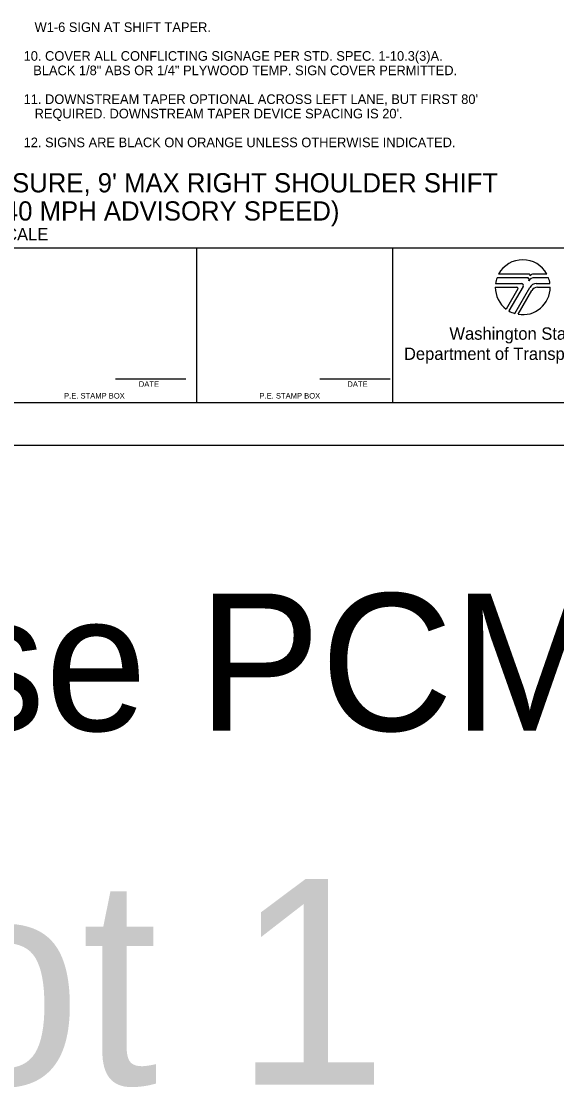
# Model space of a CAD drawing. Extents: x 99999 to 100116, y 99995 to 100013.
# Drawn here: x 100007.6 to 100011.5, y 99995.01 to 100002.78 of the extents above; entities that cross this region are included whole.
import ezdxf

# ---------------------------------------------------------------- set-up
doc = ezdxf.new("R2010")
doc.units = 0
for name, color, linetype in [('SH_DE_DetailHeading1Text', 7, 'Continuous'), ('SH_GI_GeneralNotesBodyText', 7, 'Continuous'), ('SH_GI_PlotLimits', 7, 'Continuous'), ('SH_GI_SheetBorder', 7, 'Continuous'), ('SH_GI_SheetLocationText', 7, 'Continuous'), ('SH_GI_SheetTextInCells', 7, 'Continuous'), ('SH_GI_WSDOTLogo', 7, 'Continuous')]:
    doc.layers.add(name, color=color, linetype=linetype)

msp = doc.modelspace()

# ---------------------------------------------------------------- linework, layer by layer
at = {"layer": 'SH_GI_PlotLimits'}
msp.add_lwpolyline([(99999.0625, 99999.6875), (100016.0625, 99999.6875), (100016.0625, 100010.6875), (99999.0625, 100010.6875)], close=True, dxfattribs=at)
at = {"layer": 'SH_GI_SheetBorder'}
for p, q in [((100000, 100001.1259), (100015.75, 100001.1259)), ((100008.8828, 100000), (100008.8828, 100001.1259)), ((100010.3089, 100001.1259), (100010.3089, 100000)), ((100008.2903, 100000.1733), (100008.802, 100000.1733)), ((100009.7797, 100000.1733), (100010.2914, 100000.1733)), ((100000, 100000), (100015.75, 100000))]:
    msp.add_line(p, q, dxfattribs=at)
at = {"layer": 'SH_GI_WSDOTLogo'}
for p, q in [((100011.059, 100000.8661), (100011.2496, 100000.8661)), ((100011.2894, 100000.9094), (100011.0697, 100000.9094)), ((100011.303, 100000.9354), (100011.0815, 100000.9354)), ((100011.433, 100000.9354), (100011.3351, 100000.9354)), ((100011.343, 100000.9094), (100011.3429, 100000.9094)), ((100011.4448, 100000.9094), (100011.343, 100000.9094)), ((100011.3558, 100000.8661), (100011.4555, 100000.8661)), ((100011.0572, 100000.84), (100011.2148, 100000.84)), ((100011.222, 100000.8277), (100011.1364, 100000.6807)), ((100011.261, 100000.8464), (100011.1567, 100000.6672)), ((100011.1989, 100000.6487), (100011.3089, 100000.839)), ((100011.2244, 100000.6428), (100011.3242, 100000.8156)), ((100011.3655, 100000.8394), (100011.4572, 100000.8394))]:
    msp.add_line(p, q, dxfattribs=at)
for centre, radius, start, end in [((100011.2572, 100000.84), 0.2, 28.47865, 151.53204), ((100011.2572, 100000.84), 0.2, 159.69598, 172.50569), ((100011.2497, 100000.853), 0.0131, 329.76834, 90), ((100011.2894, 100000.8946), 0.0148, 327.8418, 89.99855), ((100011.3429, 100000.861), 0.0484, 89.99529, 147.82376), ((100011.303, 100000.9263), 0.00903, 329.87418, 90.00328), ((100011.3558, 100000.8119), 0.0542, 90, 149.99738), ((100011.3352, 100000.9066), 0.0287, 90.00721, 148.16763), ((100011.2572, 100000.84), 0.2, 7.49431, 20.29406), ((100011.2572, 100000.84), 0.2, 179.99864, 232.84327), ((100011.2149, 100000.8318), 0.0082, 329.74356, 90), ((100011.2572, 100000.84), 0.2, 260.54554, 359.80857), ((100011.3654, 100000.7918), 0.0476, 90, 150.05432), ((100011.2572, 100000.84), 0.2, 239.79292, 253.0448)]:
    msp.add_arc(centre, radius, start, end, dxfattribs=at)

# ---------------------------------------------------------------- texts
at = {"layer": 'SH_DE_DetailHeading1Text'}
for s, height, p in [("FREEWAY (2 LANES): SINGLE LEFT LANE CLOSURE, 9' MAX RIGHT SHOULDER SHIFT", 0.14, (100003.3853, 100001.5312)), ('(55 MPH WORK ZONE SPEED LIMIT, 40 MPH ADVISORY SPEED)', 0.14, (100004.2106, 100001.3259)), ('NOT TO SCALE', 0.09, (100006.9175, 100001.1809))]:
    msp.add_text(s, height=height, rotation=360, dxfattribs=at).set_placement(p)
at = {"layer": 'SH_GI_GeneralNotesBodyText'}
for s, p in [('W1-6 SIGN AT SHIFT TAPER.', (100007.7004, 100002.7006)), ('10. COVER ALL CONFLICTING SIGNAGE PER STD. SPEC. 1-10.3(3)A.', (100007.6204, 100002.4906)), ('BLACK 1/8" ABS OR 1/4" PLYWOOD TEMP. SIGN COVER PERMITTED.', (100007.6904, 100002.3856)), ("11. DOWNSTREAM TAPER OPTIONAL ACROSS LEFT LANE, BUT FIRST 80' ", (100007.6204, 100002.1756)), ("REQUIRED. DOWNSTREAM TAPER DEVICE SPACING IS 20'.", (100007.7004, 100002.0706)), ('12. SIGNS ARE BLACK ON ORANGE UNLESS OTHERWISE INDICATED.', (100007.6204, 100001.8606))]:
    msp.add_text(s, height=0.07, rotation=360, dxfattribs=at).set_placement(p)
at = {"layer": 'SH_GI_SheetLocationText'}
for s, height, p in [('3-Phase PCMS', 1, (100003.5395, 99997.6071)), ('Plot 1', 1.5, (100005.1422, 99995.0267))]:
    msp.add_text(s, height=height, dxfattribs=at).set_placement(p)
at = {"layer": 'SH_GI_SheetTextInCells'}
for s, height, p in [('Washington State', 0.090072, (100010.7229, 100000.4571)), ('Department of Transportation', 0.090072, (100010.3916, 100000.3101)), ('DATE', 0.04003, (100008.4597, 100000.1141)), ('DATE', 0.04003, (100009.9794, 100000.1141)), ('P.E. STAMP BOX', 0.040032, (100007.915, 100000.0286)), ('P.E. STAMP BOX', 0.040032, (100009.339, 100000.0286))]:
    msp.add_text(s, height=height, dxfattribs=at).set_placement(p)

doc.saveas('drawing.dxf')
